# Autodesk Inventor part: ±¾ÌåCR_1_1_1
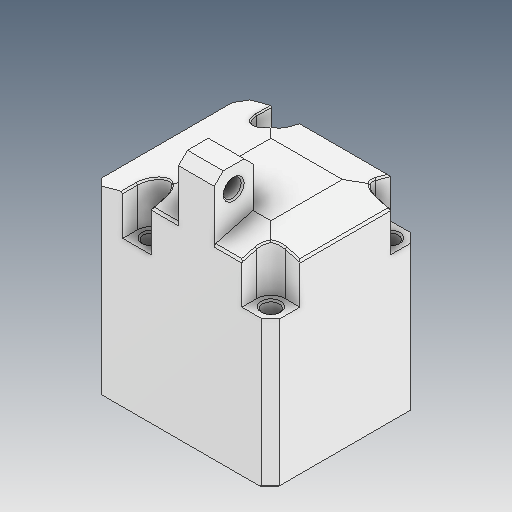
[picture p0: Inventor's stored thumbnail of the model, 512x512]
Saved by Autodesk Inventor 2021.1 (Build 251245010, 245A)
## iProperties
Created: 2021-05
Part Number: ±¾ÌåCR_1_1_1
Material: Ogólny
Document SubType Name: Modeling
Designer: user
Density: 1 g/cm^3
Appearance: Domyślna
Author: user
Revision Number: ÈÎºÎ
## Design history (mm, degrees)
feature "ÊäÈë1"
node "Bryła1"
